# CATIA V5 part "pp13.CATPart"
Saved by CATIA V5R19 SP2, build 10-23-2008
Part number: pp13
Bounding box of the stored display mesh (mm): x 10 to 15, y -102.25 to 75.133, z -52.25 to 37.913
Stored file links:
  C:\Users\Welcome\Documents\thinkm2\pp13.CATPart
  C:\Users\Welcome\Documents\thinkm2\Brasmeca.CATProduct
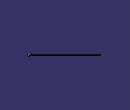
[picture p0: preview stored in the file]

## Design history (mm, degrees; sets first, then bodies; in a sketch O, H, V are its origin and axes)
AxisSystem1: origin (0, 0, 0), X (1, 0, 0), Y (0, 1, 0), Z (0, 0, 1)
Set1
  Plane1: linked copy from another document
  Line1: linked copy from another document
  Plane2: linked copy from another document
Body1 (main body)
  Sketch1 on Plane1, origin (15, 0, 0), H (0, 1, 0), V (0, 0, 1)
    circle A1 centre (-100, -50) radius 2.25
    reference projected point E1 (-100, -50) from Line1
    radius A1 = 2.25
    distance A1 E1 = 2.25
  Pad1: profile Sketch1, direction (-1, 0, 0), length 5
  Sketch2 on Plane2, origin (0, 50, 25), H (1, 0, 0), V (0, -0.4472, 0.8944)
    line L1 (13.1602, 0.4627) -> (14.8259, 0.4627)
    line L2 (14.8259, 0.4627) -> (14.8259, -0.2992)
    line L3 (14.8259, -0.2992) -> (13.1602, -0.2992)
    line L4 (13.1602, -0.2992) -> (13.1602, 0.4627)
    length L1 = 1.6656
    length L2 = 0.7619
  Pad2: profile Sketch2, direction (0, -0.8944, -0.4472), length 167
  Pad3: profile Sketch2, direction (0, 0.8944, 0.4472), length 27.95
